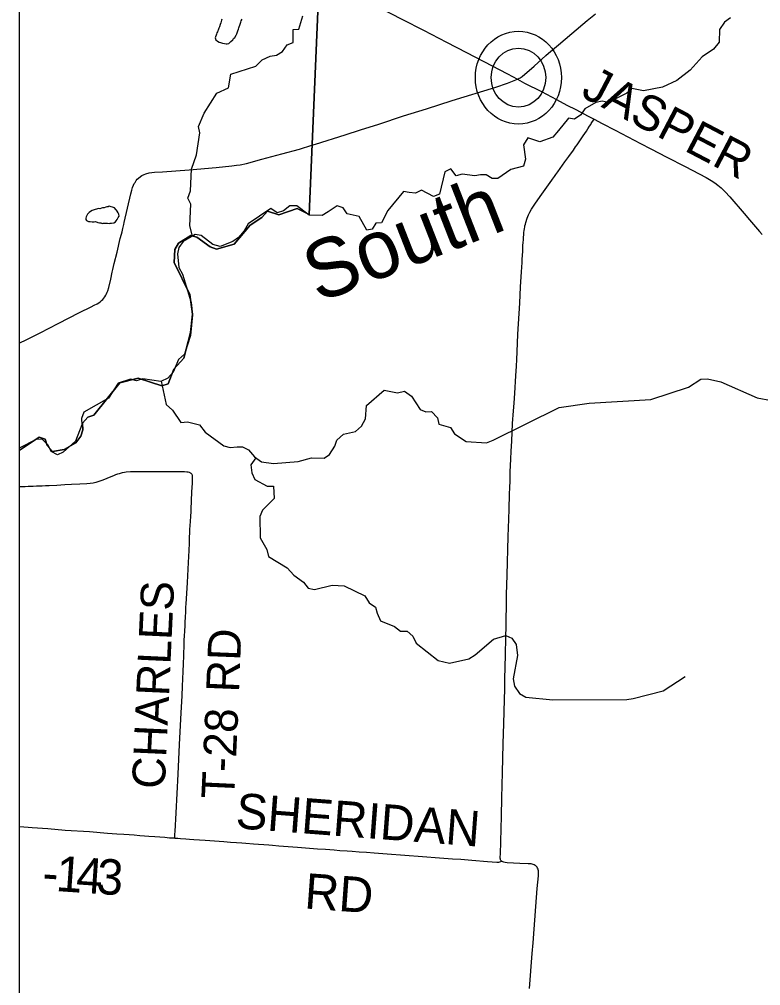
# Model space of a CAD drawing. Extents: x -13.9 to 69.1, y -25.2 to 26.1.
# Drawn here: x 1.757 to 2.896, y 14.961 to 16.445 of the extents above; entities that cross this region are included whole.
import ezdxf

# ---------------------------------------------------------------- set-up
doc = ezdxf.new("R2010")
doc.units = 0
for name, color, linetype in [('GM_X_County_Road', 7, 'Continuous'), ('GM_X_County_Road_Text', 7, 'Continuous'), ('GM_X_Minor_Lake', 7, 'Continuous'), ('GM_X_Minor_River', 7, 'Continuous'), ('GM_X_Minor_River_Text', 7, 'Continuous'), ('GM_X_Township', 7, 'Continuous'), ('GM_X_Township_Road', 7, 'Continuous'), ('GM_X_Township_Road_Text', 7, 'Continuous'), ('GM_X_Unincorporated', 7, 'Continuous'), ('GM_X_Unincorporated_Location', 7, 'Continuous'), ('SH_Data', 7, 'Continuous')]:
    doc.layers.add(name, color=color, linetype=linetype)

msp = doc.modelspace()

# ---------------------------------------------------------------- linework, layer by layer
at = {"layer": 'GM_X_County_Road'}
for points in [[(2.2454, 16.4958), (2.2599, 16.4882), (2.2774, 16.4793), (2.291, 16.4726), (2.346, 16.4446), (2.3783, 16.4279), (2.4137, 16.4096), (2.4441, 16.3939), (2.471, 16.3799), (2.5073, 16.3611), (2.5227, 16.3528)], [(2.5227, 16.3528), (2.5257, 16.3542), (2.5271, 16.3551), (2.5283, 16.3559), (2.5295, 16.3568), (2.5482, 16.373), (2.566, 16.389), (2.5703, 16.3928), (2.5855, 16.4056), (2.6058, 16.4231), (2.6298, 16.4431), (2.6422, 16.4531)], [(2.2066, 16.2513), (2.2124, 16.2531), (2.258, 16.2675), (2.2812, 16.2751), (2.3093, 16.284), (2.3475, 16.2963), (2.3825, 16.3073), (2.4222, 16.3199), (2.4891, 16.3408), (2.5071, 16.3468), (2.5123, 16.3488), (2.5227, 16.3528)], [(2.5227, 16.3528), (2.5334, 16.3469), (2.5593, 16.3337), (2.5826, 16.3214), (2.5985, 16.3131), (2.612, 16.3061), (2.6313, 16.2958), (2.6404, 16.2912)], [(2.4982, 15.1517), (2.4976, 15.1522), (2.497, 15.153), (2.4965, 15.1539), (2.4963, 15.1549), (2.4961, 15.1562), (2.4961, 15.1583), (2.4963, 15.1624), (2.4979, 15.2207), (2.4986, 15.2492), (2.4996, 15.2878), (2.5007, 15.3318), (2.5015, 15.3633), (2.5024, 15.3996), (2.5029, 15.4162), (2.5033, 15.4317), (2.5037, 15.4495), (2.5041, 15.4686), (2.5047, 15.4953), (2.5051, 15.5131), (2.5053, 15.5274), (2.5055, 15.5393), (2.5059, 15.5613), (2.5066, 15.591), (2.5083, 15.6504), (2.5092, 15.6772), (2.5096, 15.6926), (2.5104, 15.7152), (2.5107, 15.7259), (2.5111, 15.7354), (2.5115, 15.7497), (2.5122, 15.7692), (2.5127, 15.7817), (2.5136, 15.7971), (2.5151, 15.8238), (2.5165, 15.8434), (2.5173, 15.8552), (2.5183, 15.8707), (2.52, 15.8973), (2.5208, 15.9122), (2.5213, 15.9222), (2.5219, 15.9341), (2.5232, 15.9614), (2.5259, 16.0089), (2.5273, 16.0338), (2.5288, 16.057), (2.5296, 16.0712), (2.5299, 16.0766), (2.5305, 16.0884), (2.531, 16.0967), (2.5314, 16.1026), (2.5316, 16.1056), (2.5318, 16.1104), (2.5321, 16.1139), (2.5324, 16.1174), (2.5327, 16.1204), (2.5331, 16.1232), (2.5336, 16.1259), (2.534, 16.1277), (2.5346, 16.13), (2.5353, 16.1328), (2.5376, 16.1394), (2.5396, 16.1443), (2.5415, 16.1485), (2.544, 16.1531), (2.5461, 16.1564), (2.5503, 16.1626), (2.56, 16.1763), (2.5729, 16.1941), (2.5752, 16.1975), (2.5765, 16.1993), (2.5795, 16.2036), (2.5815, 16.2065), (2.5846, 16.2107), (2.5953, 16.2257), (2.5984, 16.2299), (2.6015, 16.2341), (2.6086, 16.244), (2.6119, 16.2487), (2.6142, 16.2521), (2.6204, 16.2612), (2.6236, 16.266), (2.6259, 16.2694), (2.6285, 16.2732), (2.6307, 16.2766), (2.6332, 16.2805), (2.6351, 16.2834), (2.636, 16.2847), (2.6404, 16.2912)], [(2.6404, 16.2912), (2.6528, 16.2849), (2.6726, 16.2746), (2.7117, 16.2542)], [(2.7117, 16.2542), (2.7273, 16.246), (2.7521, 16.233), (2.7801, 16.2186), (2.8124, 16.2018), (2.8203, 16.1974), (2.826, 16.1937), (2.8306, 16.1903), (2.8354, 16.1861), (2.8415, 16.18), (2.8489, 16.1719), (2.8706, 16.1466), (2.8789, 16.137), (2.8942, 16.119), (2.8984, 16.1143)], [(1.7571, 15.9472), (1.7687, 15.953), (1.7892, 15.9635), (1.8166, 15.9776), (1.8496, 15.9944), (1.8676, 16.0034), (1.8722, 16.0055), (1.8767, 16.0079), (1.8791, 16.0094), (1.8815, 16.011), (1.8835, 16.0127), (1.8854, 16.0145), (1.8871, 16.0166), (1.8887, 16.0187), (1.8901, 16.021), (1.8912, 16.023), (1.8922, 16.0256), (1.893, 16.0279), (1.8945, 16.0331), (1.8976, 16.0458), (1.8999, 16.0562), (1.9008, 16.0603), (1.9028, 16.0695), (1.9072, 16.0873), (1.9123, 16.108), (1.914, 16.1149), (1.9149, 16.1183), (1.9161, 16.1235), (1.9177, 16.1298), (1.9184, 16.1326), (1.9285, 16.1765), (1.9298, 16.1822), (1.9312, 16.1866), (1.9327, 16.1903), (1.9338, 16.1925), (1.9349, 16.1943), (1.9368, 16.1972), (1.9384, 16.1992), (1.9402, 16.201), (1.9434, 16.2035), (1.9454, 16.2048), (1.9489, 16.2064), (1.9513, 16.2073), (1.9566, 16.2088), (1.9646, 16.2099), (1.9773, 16.2107), (2.0181, 16.2138), (2.0594, 16.2174), (2.0838, 16.2197), (2.0908, 16.2206), (2.0962, 16.2214), (2.1061, 16.2235), (2.1296, 16.2298), (2.1607, 16.238), (2.1874, 16.2455), (2.2066, 16.2513)], [(2.5411, 14.9564), (2.5452, 15.0097), (2.5464, 15.0263), (2.5507, 15.082), (2.553, 15.1099), (2.5546, 15.1294), (2.5547, 15.1329), (2.5549, 15.1352), (2.5548, 15.1368), (2.5544, 15.1386), (2.5542, 15.1395), (2.5535, 15.141), (2.5526, 15.1426), (2.5514, 15.1441), (2.5509, 15.1444), (2.5498, 15.1452), (2.5484, 15.146), (2.5468, 15.1467), (2.5453, 15.1471), (2.5434, 15.1475), (2.5389, 15.1479), (2.5261, 15.1484), (2.5068, 15.1494), (2.5035, 15.1497), (2.5014, 15.1501), (2.5, 15.1506), (2.4991, 15.151), (2.4983, 15.1515), (2.4982, 15.1517)]]:
    msp.add_lwpolyline(points, dxfattribs=at)
at = {"layer": 'GM_X_Minor_Lake'}
for points in [[(2.0684, 16.4451), (2.0677, 16.4433), (2.067, 16.4415), (2.0667, 16.4393), (2.0656, 16.4368), (2.0646, 16.4332), (2.0639, 16.4314), (2.0632, 16.4296), (2.0618, 16.4256), (2.0608, 16.4238), (2.0601, 16.422), (2.058, 16.4162), (2.059, 16.4133), (2.0617, 16.4114), (2.064, 16.4096), (2.0664, 16.4092), (2.0691, 16.4084), (2.0724, 16.4076), (2.0748, 16.4073), (2.0765, 16.4069), (2.0789, 16.4079), (2.0806, 16.4094), (2.0823, 16.4108), (2.085, 16.4133), (2.0864, 16.4151), (2.0881, 16.4169), (2.0901, 16.4202), (2.0912, 16.4227), (2.0929, 16.4271), (2.0939, 16.4296), (2.0943, 16.4318), (2.0964, 16.4376), (2.0977, 16.4404), (2.0981, 16.4426), (2.0995, 16.4452)], [(1.9079, 16.1496), (1.9032, 16.1551), (1.9002, 16.1562), (1.8982, 16.1569), (1.8951, 16.1577), (1.8934, 16.157), (1.8917, 16.1567), (1.89, 16.1563), (1.8873, 16.1552), (1.885, 16.1553), (1.8833, 16.1549), (1.8809, 16.1539), (1.8789, 16.1543), (1.8755, 16.1532), (1.8735, 16.1529), (1.8691, 16.1511), (1.8667, 16.1497), (1.8646, 16.1482), (1.8619, 16.1454), (1.8609, 16.1435), (1.8599, 16.1414), (1.8595, 16.1396), (1.8591, 16.1374), (1.8605, 16.1356), (1.8635, 16.1344), (1.8662, 16.134), (1.8689, 16.1336), (1.8719, 16.1336), (1.874, 16.134), (1.8777, 16.1328), (1.8804, 16.1324), (1.8824, 16.132), (1.8844, 16.1313), (1.8861, 16.1316), (1.8885, 16.1316), (1.8905, 16.1316), (1.8928, 16.1316), (1.8949, 16.1312), (1.8966, 16.1315), (1.8989, 16.1319), (1.9023, 16.1322), (1.905, 16.1336), (1.906, 16.1354), (1.9074, 16.1372), (1.9091, 16.1405), (1.9105, 16.1423), (1.9102, 16.1455), (1.9089, 16.1474), (1.9079, 16.1492), (1.9079, 16.1492), (1.9079, 16.1496)]]:
    msp.add_lwpolyline(points, dxfattribs=at)
at = {"layer": 'GM_X_Minor_River'}
for points in [[(2.0232, 16.1118), (2.0189, 16.1277), (2.0204, 16.1608), (2.0161, 16.1699), (2.0203, 16.1811), (2.0218, 16.2145), (2.0295, 16.2366), (2.0347, 16.2706), (2.0325, 16.2801), (2.0409, 16.3007), (2.0606, 16.3316), (2.0786, 16.3393), (2.0822, 16.3603), (2.1205, 16.3727), (2.1301, 16.3824), (2.1423, 16.3884), (2.1525, 16.3897), (2.1613, 16.3953), (2.1689, 16.4054), (2.1777, 16.4092), (2.178, 16.4292), (2.1864, 16.4298), (2.1928, 16.4504)], [(2.8499, 16.447), (2.8404, 16.4402), (2.8328, 16.4294), (2.8322, 16.4095), (2.8239, 16.3991), (2.8062, 16.387), (2.7877, 16.3666), (2.7672, 16.3506), (2.7452, 16.3408), (2.7164, 16.3347), (2.6982, 16.3383), (2.6897, 16.3308), (2.6618, 16.3171), (2.6524, 16.319), (2.643, 16.317), (2.626, 16.3075), (2.6201, 16.2981), (2.6102, 16.2914), (2.6011, 16.293), (2.5853, 16.274), (2.5771, 16.264), (2.5571, 16.2567), (2.5383, 16.2628), (2.5317, 16.252), (2.5351, 16.2298), (2.5316, 16.2193), (2.5123, 16.2142), (2.4922, 16.2003), (2.4834, 16.2001), (2.4744, 16.2061), (2.4656, 16.2058), (2.4572, 16.2042), (2.4373, 16.2067), (2.4281, 16.2043), (2.4202, 16.2149), (2.4107, 16.2104), (2.4025, 16.1763), (2.3936, 16.1729), (2.3749, 16.1822), (2.366, 16.178), (2.3563, 16.1789), (2.3475, 16.1805), (2.3235, 16.1511), (2.3138, 16.1324), (2.305, 16.1318), (2.2995, 16.1224), (2.291, 16.1208), (2.2795, 16.1417), (2.261, 16.146), (2.2547, 16.1551), (2.2457, 16.1582), (2.2314, 16.149), (2.2225, 16.1437), (2.2023, 16.144), (2.1836, 16.1581)], [(2.1836, 16.1581), (2.1725, 16.1583), (2.1632, 16.1505), (2.1531, 16.1477), (2.1434, 16.154), (2.1087, 16.1306), (2.1024, 16.1198), (2.0938, 16.1098), (2.085, 16.1034), (2.0657, 16.0961), (2.0546, 16.0988), (2.0365, 16.1126), (2.0275, 16.1142), (2.0088, 16.1036), (2.0022, 16.0942), (2, 16.0845), (2.0024, 16.0637), (2.008, 16.0534), (2.0209, 16.01), (2.023, 15.9907), (2.0202, 15.9592), (2.0107, 15.9306), (2.0018, 15.9224), (1.9934, 15.9029), (1.9852, 15.8936), (1.9747, 15.8887), (1.9471, 15.8928), (1.9372, 15.8897), (1.9278, 15.892), (1.9088, 15.8858), (1.8943, 15.8631), (1.8563, 15.8412), (1.8527, 15.8315), (1.8529, 15.8217), (1.8435, 15.7968), (1.8247, 15.78), (1.8159, 15.7761), (1.8061, 15.781), (1.8016, 15.7905), (1.7922, 15.8001), (1.7831, 15.7992), (1.7571, 15.7862)], [(1.9751, 15.8889), (1.9826, 15.853), (1.9926, 15.8445), (2.0055, 15.8257), (2.0156, 15.8266), (2.0341, 15.822), (2.0424, 15.8109), (2.0711, 15.7898), (2.0812, 15.7871), (2.0916, 15.788), (2.1001, 15.7882), (2.1094, 15.7837), (2.1184, 15.7726), (2.1291, 15.7652), (2.1479, 15.7624), (2.1858, 15.7657), (2.2058, 15.7712), (2.2253, 15.7705), (2.2338, 15.7766), (2.2421, 15.7892), (2.2449, 15.7986), (2.2552, 15.8078), (2.2735, 15.8115), (2.283, 15.8201), (2.2892, 15.8309), (2.2906, 15.8516), (2.3175, 15.8751), (2.3384, 15.8711), (2.3489, 15.8735), (2.3599, 15.8661), (2.3728, 15.8455), (2.3815, 15.8417), (2.3903, 15.8423), (2.3996, 15.8327), (2.4018, 15.8232), (2.4196, 15.8179), (2.4256, 15.8083), (2.4439, 15.7964), (2.4749, 15.7941), (2.4851, 15.7986), (2.5864, 15.8486), (2.6327, 15.8554), (2.7275, 15.8608), (2.7855, 15.8798), (2.8042, 15.8919), (2.8147, 15.8924), (2.8349, 15.8878), (2.8909, 15.8636), (2.9349, 15.8552)], [(2.1204, 15.7713), (2.1128, 15.7604), (2.1143, 15.7484), (2.1189, 15.7381), (2.138, 15.7276), (2.1478, 15.7275), (2.1489, 15.7086), (2.1307, 15.6907), (2.1265, 15.6813), (2.1271, 15.6486), (2.1376, 15.6303), (2.1398, 15.6197), (2.1686, 15.6022), (2.1788, 15.5909)], [(2.1788, 15.5909), (2.1936, 15.5804), (2.2009, 15.5712), (2.2104, 15.5689), (2.2378, 15.5757), (2.256, 15.5744), (2.2882, 15.5594), (2.2945, 15.5484), (2.3042, 15.5418), (2.3068, 15.5326), (2.3121, 15.5209), (2.3336, 15.5123), (2.3426, 15.5052), (2.3531, 15.5051), (2.3618, 15.4974), (2.367, 15.4867), (2.4005, 15.4598), (2.4183, 15.4559), (2.4478, 15.4624), (2.4576, 15.4688), (2.4856, 15.4927), (2.5045, 15.4983), (2.5136, 15.4942), (2.5206, 15.4846), (2.5224, 15.4675), (2.5159, 15.4316), (2.5178, 15.4207), (2.5255, 15.4093), (2.5352, 15.4034), (2.577, 15.3995), (2.6904, 15.4001), (2.7005, 15.4014), (2.7465, 15.4135), (2.7802, 15.4356)]]:
    msp.add_lwpolyline(points, dxfattribs=at)
at = {"layer": 'GM_X_Township'}
for points in [[(1.7571, 19.5083), (1.7571, 15.7823), (1.7878, 15.8031), (1.7966, 15.7997), (1.7999, 15.7902), (1.8082, 15.781), (1.8261, 15.784), (1.8441, 15.7943), (1.8517, 15.8044), (1.8545, 15.8142), (1.8543, 15.8243), (1.8625, 15.8337), (1.8716, 15.8368), (1.9113, 15.8865), (1.9398, 15.8937), (1.9761, 15.882), (1.9859, 15.8851), (1.9946, 15.9072), (2.0097, 15.9244), (2.0199, 15.9639), (2.0233, 15.9918), (2.0189, 16.0221), (1.9952, 16.0711), (1.9961, 16.0914), (2.0019, 16.1008), (2.0206, 16.1129), (2.0297, 16.1102), (2.0505, 16.0951), (2.0599, 16.0917), (2.087, 16.0993), (2.1116, 16.1284), (2.1296, 16.1402), (2.1382, 16.1499), (2.156, 16.1445), (2.1841, 16.1543), (2.2023, 16.145), (2.216, 16.457)], [(2.216, 16.457), (2.2023, 16.145), (2.1841, 16.1543), (2.156, 16.1445), (2.1382, 16.1499), (2.1296, 16.1402), (2.1116, 16.1284), (2.087, 16.0993), (2.0599, 16.0917), (2.0505, 16.0951), (2.0297, 16.1102), (2.0206, 16.1129), (2.0019, 16.1008), (1.9961, 16.0914), (1.9952, 16.0711), (2.0189, 16.0221), (2.0233, 15.9918), (2.0199, 15.9639), (2.0097, 15.9244), (1.9946, 15.9072), (1.9859, 15.8851), (1.9761, 15.882), (1.9398, 15.8937), (1.9113, 15.8865), (1.8716, 15.8368), (1.8625, 15.8337), (1.8543, 15.8243), (1.8545, 15.8142), (1.8517, 15.8044), (1.8441, 15.7943), (1.8261, 15.784), (1.8082, 15.781), (1.7999, 15.7902), (1.7966, 15.7997), (1.7878, 15.8031), (1.7571, 15.7823), (1.7571, 14.6812)]]:
    msp.add_lwpolyline(points, dxfattribs=at)
at = {"layer": 'GM_X_Township_Road'}
for points in [[(2.0233, 15.7366), (2.0231, 15.7417), (2.0231, 15.7438), (2.023, 15.7444), (2.0227, 15.7452), (2.022, 15.7464), (2.0213, 15.7473), (2.0203, 15.7479), (2.0196, 15.7483), (2.0188, 15.7485), (2.0166, 15.7491), (2.0146, 15.7493), (2.0111, 15.7496), (2.0054, 15.7498), (1.9962, 15.7497), (1.9892, 15.7498), (1.9785, 15.7495), (1.9666, 15.7495), (1.9517, 15.7497), (1.9441, 15.7496), (1.9385, 15.7496), (1.9278, 15.7497), (1.9211, 15.7493), (1.9185, 15.7489), (1.9151, 15.7481), (1.9119, 15.7473), (1.9103, 15.7468), (1.9082, 15.7462), (1.905, 15.7451), (1.9016, 15.7438), (1.8951, 15.741), (1.8917, 15.7394), (1.8882, 15.7379), (1.884, 15.7364), (1.881, 15.7352), (1.8778, 15.7342), (1.8749, 15.7334), (1.8704, 15.7325), (1.8657, 15.7319), (1.8606, 15.7313), (1.8499, 15.7306), (1.8374, 15.7301), (1.8271, 15.7296), (1.8147, 15.7289), (1.8028, 15.7283), (1.7973, 15.728), (1.7924, 15.7277), (1.7835, 15.7275), (1.7785, 15.7272), (1.7742, 15.7271), (1.7709, 15.7271), (1.7661, 15.7268), (1.7596, 15.7268)], [(1.9962, 15.1873), (1.9963, 15.1931), (1.9964, 15.1973), (1.9979, 15.2258), (2.001, 15.2852), (2.0034, 15.331), (2.0059, 15.3797), (2.0071, 15.4058), (2.0079, 15.4207), (2.0089, 15.4432), (2.0094, 15.4548), (2.0099, 15.467), (2.0104, 15.4855), (2.0106, 15.4902), (2.011, 15.4991), (2.0112, 15.5039), (2.0118, 15.5145), (2.0121, 15.5205), (2.0123, 15.5252), (2.0129, 15.5365), (2.0132, 15.5424), (2.0134, 15.5466), (2.0153, 15.5798), (2.0168, 15.6107), (2.0181, 15.6291), (2.0183, 15.6333), (2.0184, 15.6356), (2.0186, 15.6386), (2.0186, 15.6404), (2.0186, 15.6439), (2.0187, 15.6463), (2.0187, 15.6469), (2.0188, 15.6481), (2.0191, 15.6576), (2.0193, 15.6611), (2.0201, 15.6735), (2.0205, 15.6816), (2.0209, 15.6882), (2.0211, 15.6955), (2.0214, 15.7021), (2.0218, 15.7091), (2.022, 15.715), (2.0222, 15.7199), (2.0225, 15.7246), (2.023, 15.7333), (2.0233, 15.7366)], [(1.7596, 15.7268), (1.7576, 15.7268), (1.7571, 15.7267)], [(1.7571, 15.2051), (1.7577, 15.2051), (1.7767, 15.2036), (1.8009, 15.2017), (1.8274, 15.1996), (1.8649, 15.1971), (1.8925, 15.195), (1.9068, 15.1939), (1.9178, 15.1931), (1.9261, 15.1926), (1.9338, 15.192), (1.9421, 15.1914), (1.9492, 15.1908), (1.9559, 15.1903), (1.9652, 15.1896), (1.9805, 15.1884), (1.9879, 15.1878), (1.9944, 15.1874), (1.9962, 15.1873)], [(1.9962, 15.1873), (2.0005, 15.187), (2.0049, 15.1867), (2.0132, 15.1861), (2.0187, 15.1857), (2.0253, 15.1852), (2.0424, 15.1839), (2.0496, 15.1834), (2.0711, 15.1818), (2.0815, 15.181), (2.0909, 15.1803), (2.0991, 15.1797), (2.1052, 15.1792), (2.1168, 15.1785), (2.1405, 15.1766), (2.146, 15.1761), (2.1559, 15.1753), (2.1844, 15.1732), (2.2155, 15.1708), (2.2278, 15.17), (2.2408, 15.169), (2.2496, 15.1683), (2.2607, 15.1675), (2.2684, 15.167), (2.2794, 15.1662), (2.2904, 15.1654), (2.3025, 15.1645), (2.3157, 15.1635), (2.329, 15.1625), (2.3427, 15.1616), (2.3559, 15.1605), (2.3697, 15.1595), (2.383, 15.1585), (2.3962, 15.1574), (2.4094, 15.1565), (2.4225, 15.1555), (2.4356, 15.1546), (2.4524, 15.1533), (2.4767, 15.1514), (2.491, 15.1503), (2.4923, 15.1502), (2.4937, 15.1503), (2.4954, 15.1506), (2.497, 15.1512), (2.4982, 15.1517)]]:
    msp.add_lwpolyline(points, dxfattribs=at)
at = {"layer": 'GM_X_Unincorporated'}
for major_axis in [(0, 0.0712), (0, 0.0451)]:
    msp.add_ellipse((2.524, 16.3552), major_axis=major_axis, ratio=0.929448, dxfattribs=at)
at = {"layer": 'GM_X_Unincorporated_Location'}
msp.add_line((2.524, 16.3552), (2.524, 16.3552), dxfattribs=at)
at = {"layer": 'SH_Data'}
msp.add_line((1.7571, 21.2145), (1.7571, 14.4145), dxfattribs=at)

# ---------------------------------------------------------------- texts
at = {"layer": 'GM_X_County_Road_Text'}
msp.add_text('JASPER', height=0.05366, rotation=332.3532, dxfattribs=at).set_placement((2.618, 16.3273))
at = {"layer": 'GM_X_Minor_River_Text'}
msp.add_text('South', height=0.0899, rotation=21.3842, dxfattribs=at).set_placement((2.2162, 16.0086))
at = {"layer": 'GM_X_Township_Road_Text'}
for s, height, rotation, p in [('CHARLES', 0.05056, 87.366, (1.9805, 15.262)), ('RD', 0.05055, 87.7042, (2.0946, 15.4104)), ('T-28', 0.05056, 87.3559, (2.0872, 15.2467)), ('SHERIDAN', 0.05436, 355.6568, (2.0885, 15.2025)), ('1', 0.0544, 356.0176, (1.8122, 15.106)), ('4', 0.0544, 356.09, (1.8433, 15.1039)), ('3', 0.0544, 356.4184, (1.8747, 15.1017)), ('-', 0.0544, 355.9823, (1.7914, 15.1075)), ('RD', 0.05437, 355.8325, (2.1942, 15.0792))]:
    msp.add_text(s, height=height, rotation=rotation, dxfattribs=at).set_placement(p)

doc.saveas('drawing.dxf')
